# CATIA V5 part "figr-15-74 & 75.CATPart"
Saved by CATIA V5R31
Part number: Part1
Bounding box of the stored display mesh (mm): x -68.209 to 30, y -98.209 to 60, z 0 to 98
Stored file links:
  D:\PROJECTS\Project 2021\US EDITION\CATIA V5 6R 2021\Resources\Part Files\c15_catia_v5_6r2021_prt\figr-15-74 & 75.CATPart
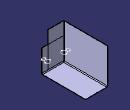
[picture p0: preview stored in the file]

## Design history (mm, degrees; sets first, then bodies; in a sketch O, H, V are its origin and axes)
SheetMetalParameters1: Thickness 1, BendRadius 2, KFactor 0.400515 {= log(min(100,max(20*SheetMetalParameters1.BendRadius,SheetMetalParameters1.Thickness)/SheetMetalParameters1.Thickness))/log(100)/2}, ReliefRadialLength 1, ReliefAxialLength 2, MinimumBendRadius 0
Body1 (main body)
  Sketch1 on xy-plane, origin (0, 0, 0), H (1, 0, 0), V (0, 1, 0)
    line L1 (-30, 60) -> (30, 60)
    line L2 (30, 60) -> (30, -60)
    line L3 (30, -60) -> (-30, -60)
    line L4 (-30, -60) -> (-30, 60)
    length L2 = 120
    length L1 = 60
    distance V L2 = 30
    distance H L1 = 60
    horizontal: L1 H, L3 H
    vertical: L2 V, L4 V
  Wall1: Thickness 1, Profile Sketch1
  d_NewWallOnEdge1: NewWallOnEdge_Edge edge [face of Wall1 | face of Wall1], NewWallOnEdge_Length 98, NewWallOnEdge_HeightLimitOffset 0, NewWallOnEdge_WidthOffset1 0, NewWallOnEdge_WidthOffset2 0, NewWallOnEdge_Angle 90, NewWallOnEdge_BendRadiusValue 2 {= SheetMetalParameters1.BendRadius}, NewWallOnEdge_BendTable SheetMetalParameters1, KFacteur 0.400515 {= log(min(100,max(20*d_NewWallOnEdge1.Radius,SheetMetalParameters1.Thickness)/SheetMetalParameters1.Thickness))/log(100)/2}
  d_NewWallOnEdge2: NewWallOnEdge_Edge edge [face of Wall1 | face of Wall1], NewWallOnEdge_Length 63, NewWallOnEdge_HeightLimitOffset 0, NewWallOnEdge_WidthOffset1 0, NewWallOnEdge_WidthOffset2 0, NewWallOnEdge_Angle 90, NewWallOnEdge_BendRadiusValue 2 {= SheetMetalParameters1.BendRadius}, NewWallOnEdge_BendTable SheetMetalParameters1, KFacteur 0.400515 {= log(min(100,max(20*d_NewWallOnEdge2.Radius,SheetMetalParameters1.Thickness)/SheetMetalParameters1.Thickness))/log(100)/2}
  d_NewWallOnEdge3: NewWallOnEdge_Edge edge [face of d_NewWallOnEdge1 | face of d_NewWallOnEdge1], NewWallOnEdge_Length 44, NewWallOnEdge_HeightLimitOffset 0, NewWallOnEdge_WidthOffset1 0, NewWallOnEdge_WidthOffset2 0, NewWallOnEdge_Angle 90, NewWallOnEdge_BendRadiusValue 2 {= SheetMetalParameters1.BendRadius}, NewWallOnEdge_BendTable SheetMetalParameters1, KFacteur 0.400515 {= log(min(100,max(20*d_NewWallOnEdge3.Radius,SheetMetalParameters1.Thickness)/SheetMetalParameters1.Thickness))/log(100)/2}
  Sketch2 on face of d_NewWallOnEdge3, origin (0, -60, 0), H (-1, 0, 0), V (0, 0, 1)
    circle A1 centre (8.1625, 34.9685) radius 4.4696
    circle A2 centre (8.1625, 23.754) radius 6.7449
    tangency: A2 A1
  SHMMapping1: CATSHMMappingContext d_NewWallOnEdge3, CATSHMMappingObject Sketch2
